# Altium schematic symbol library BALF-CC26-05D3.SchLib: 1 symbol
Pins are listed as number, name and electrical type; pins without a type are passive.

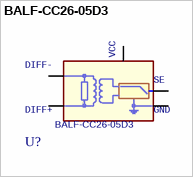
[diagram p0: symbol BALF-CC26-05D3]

## BALF-CC26-05D3
designator U?
footprint ST_CSP05N50P3X3_149X102X63
pins: A2 VCC, A3 DIFF+, B1 SE, C2 GND, C3 DIFF-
